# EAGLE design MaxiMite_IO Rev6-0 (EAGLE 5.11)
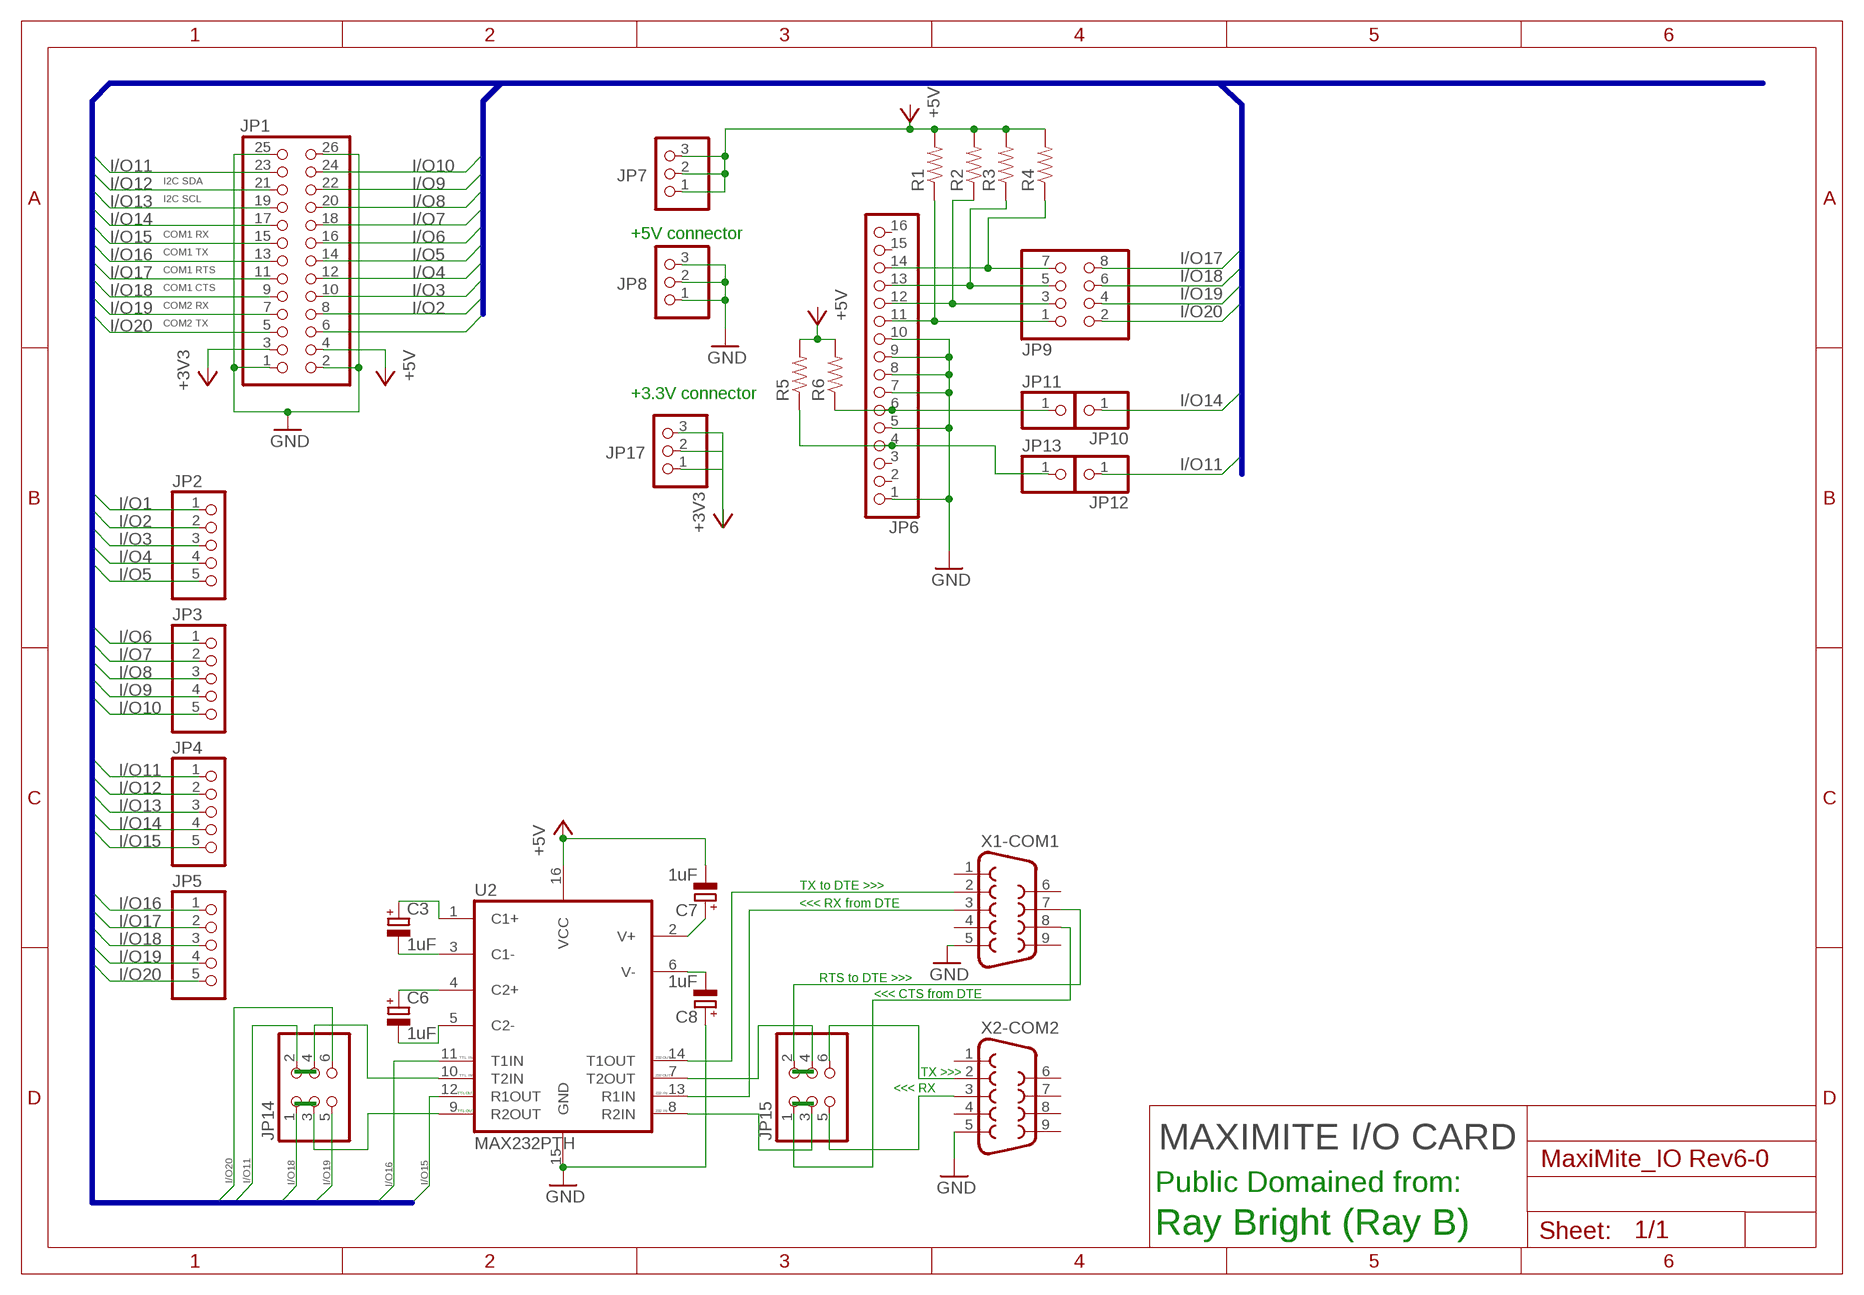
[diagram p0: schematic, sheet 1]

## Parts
C3  1uF  CPOL-EUE2,5-6E  [E2,5-6E]
C6  1uF  CPOL-EUE2,5-6E  [E2,5-6E]
C7  1uF  CPOL-EUE2,5-6E  [E2,5-6E]
C8  1uF  CPOL-EUE2,5-6E  [E2,5-6E]
JP1  PINHD-2X13  [2X13]
JP2  PINHD-1X5  [1X05]
JP3  PINHD-1X5  [1X05]
JP4  PINHD-1X5  [1X05]
JP5  PINHD-1X5  [1X05]
JP6  PINHD-1X16  [1X16]
JP7  PINHD-1X3  [1X03]
JP8  PINHD-1X3  [1X03]
JP9  PINHD-2X4  [2X04]
JP10  PINHD-1X1  [1X01]
JP11  PINHD-1X1  [1X01]
JP12  PINHD-1X1  [1X01]
JP13  PINHD-1X1  [1X01]
JP14  PINHD-2X3  [2X03]
JP15  PINHD-2X3  [2X03]
JP17  PINHD-1X3  [1X03]
R1  RESISTORPTH-1/4W  [AXIAL-0.4]
R2  RESISTORPTH-1/4W  [AXIAL-0.4]
R3  RESISTORPTH-1/4W  [AXIAL-0.4]
R4  RESISTORPTH-1/4W  [AXIAL-0.4]
R5  RESISTORPTH-1/4W  [AXIAL-0.4]
R6  RESISTORPTH-1/4W  [AXIAL-0.4]
U2  MAX232PTH  [DIL16]
X1-COM1  DB9FEMALE  [DB9]
X2-COM2  DB9FEMALE  [DB9]

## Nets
+3V3: JP1.3 JP17.1 JP17.2 JP17.3
+5V: C7.- JP1.4 JP7.1 JP7.2 JP7.3 R1.P$2 R2.P$2 R3.P$2 R4.P$2 R5.P$2 R6.P$2 U2.16(VCC)
GND: C8.+ JP1.1 JP1.2 JP1.25 JP1.26 JP6.1 JP6.5 JP6.7 JP6.8 JP6.9 JP6.10 JP8.1 JP8.2 JP8.3 U2.15(GND) X1-COM1.5 X2-COM2.5
I/O1: JP1.6 JP2.1
I/O2: JP1.8 JP2.2
I/O3: JP1.10 JP2.3
I/O4: JP1.12 JP2.4
I/O5: JP1.14 JP2.5
I/O6: JP1.16 JP3.1
I/O7: JP1.18 JP3.2
I/O8: JP1.20 JP3.3
I/O9: JP1.22 JP3.4
I/O10: JP1.24 JP3.5
I/O11: JP1.23 JP4.1 JP12.1 JP14.2
I/O12: JP1.21 JP4.2
I/O13: JP1.19 JP4.3
I/O14: JP1.17 JP4.4 JP10.1
I/O15: JP1.15 JP4.5 U2.12(R1OUT)
I/O16: JP1.13 JP5.1 U2.11(T1IN)
I/O17: JP1.11 JP5.2 JP9.8
I/O18: JP1.9 JP5.3 JP9.6 JP14.1
I/O19: JP1.7 JP5.4 JP9.4 JP14.5
I/O20: JP1.5 JP5.5 JP9.2 JP14.6
LCD_D4: JP6.11 JP9.1 R1.P$1
LCD_D5: JP6.12 JP9.3 R2.P$1
LCD_D6: JP6.13 JP9.5 R3.P$1
LCD_D7: JP6.14 JP9.7 R4.P$1
LCD_EN: JP6.6 JP11.1 R6.P$1
LCD_RS: JP6.4 JP13.1 R5.P$1
N$18: C3.+ U2.1(C1+)
N$19: C3.- U2.3(C1-)
N$20: C6.+ U2.4(C2+)
N$21: C6.- U2.5(C2-)
N$22: C8.- U2.6(V-)
N$23: C7.+ U2.2(V+)
N$24: JP14.4 U2.10(T2IN)
N$25: JP14.3 U2.9(R2OUT)
N$26: JP15.4 U2.7(T2OUT)
N$27: JP15.3 U2.8(R2IN)
N$28: JP15.6 X2-COM2.2
N$29: JP15.5 X2-COM2.3
N$30: JP15.2 X1-COM1.7
N$31: JP15.1 X1-COM1.8
N$32: U2.14(T1OUT) X1-COM1.2
N$33: U2.13(R1IN) X1-COM1.3
Unconnected: JP6.2 JP6.3 JP6.15 JP6.16 X1-COM1.1 X1-COM1.4 X1-COM1.6 X1-COM1.9 X2-COM2.1 X2-COM2.4 X2-COM2.6 X2-COM2.7 X2-COM2.8 X2-COM2.9

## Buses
I/O[1..20]

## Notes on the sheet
- I2C SDA
- I2C SCL
- COM1 RX | +5V connector
- COM1 TX
- COM1 RTS
- COM1 CTS
- COM2 RX
- COM2 TX
- +3.3V connector
- TX to DTE >>>
- <<< RX from DTE
- RTS to DTE >>>
- <<< CTS from DTE
- TTL IN | 232 OUT
- TTL IN | 232 OUT | TX >>>
- <<< RX
- TTL OUT | 232 IN
- TTL OUT | 232 IN
- MAXIMITE I/O CARD
- Public Domained from: | Freeware from:
- Ray Bright (Ray B)

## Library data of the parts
C3 C6-C8 = rcl:CPOL-EU: POLARIZED CAPACITOR, European symbol
JP1 = 0~MaxiMite:PINHD-2X13: PIN HEADER
JP2-JP5 = pinhead:PINHD-1X5: PIN HEADER
JP6 = pinhead:PINHD-1X16: PIN HEADER
JP7 JP8 JP17 = 0~MaxiMite:PINHD-1X3: PIN HEADER
JP9 = pinhead:PINHD-2X4: PIN HEADER
JP10-JP13 = pinhead:PINHD-1X1: PIN HEADER
JP14 JP15 = 0~MaxiMite:PINHD-2X3: PIN HEADER
R1-R6 = MaxiMite:RESISTOR: Resistor
U2 = 0~MaxiMite:MAX232: RS232 Transceiver Very common IC. This is generically called 'MAX232', but works with the 3V equivalent MAX3232 generic ICs. Field tested and mother approved. Spark Fun Electronics SKU : COM-00316 (DIP) and COM-00589 (SMD)
X1-COM1 X2-COM2 = 0~MaxiMite:DB9: DB9 Connector Standard DB9 (D-Sub 9) serial connector. Can be used for CAN bus as well as RS485 and RS232. Footprint production proven. Spark Fun Electronics SKU : PRT-00429

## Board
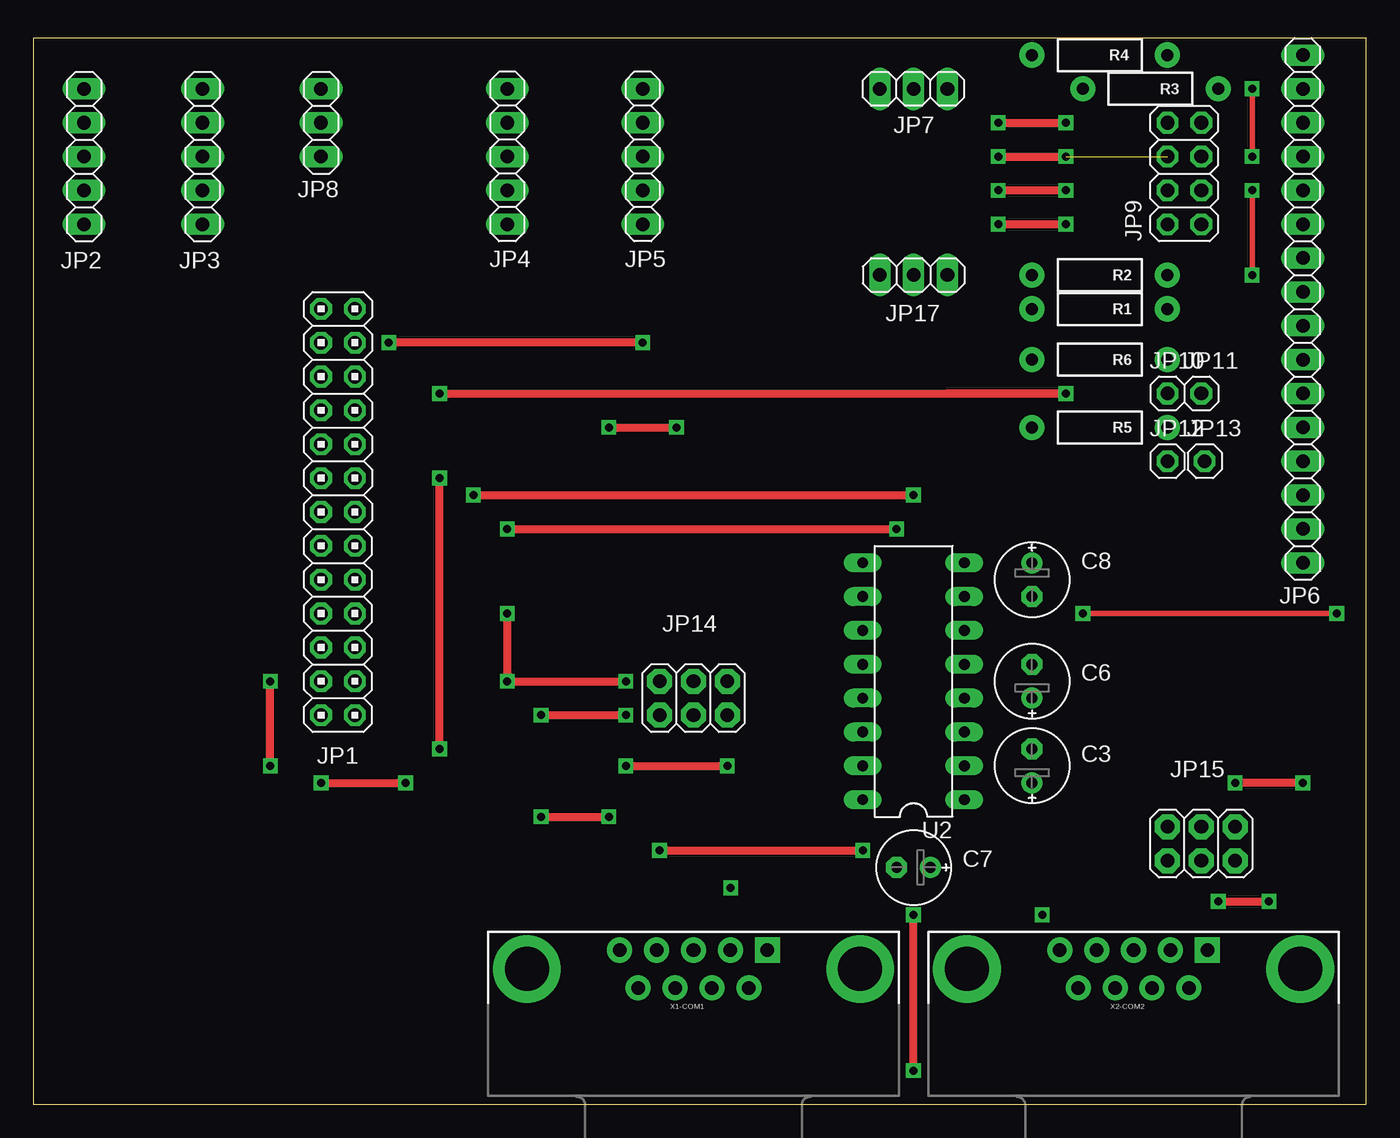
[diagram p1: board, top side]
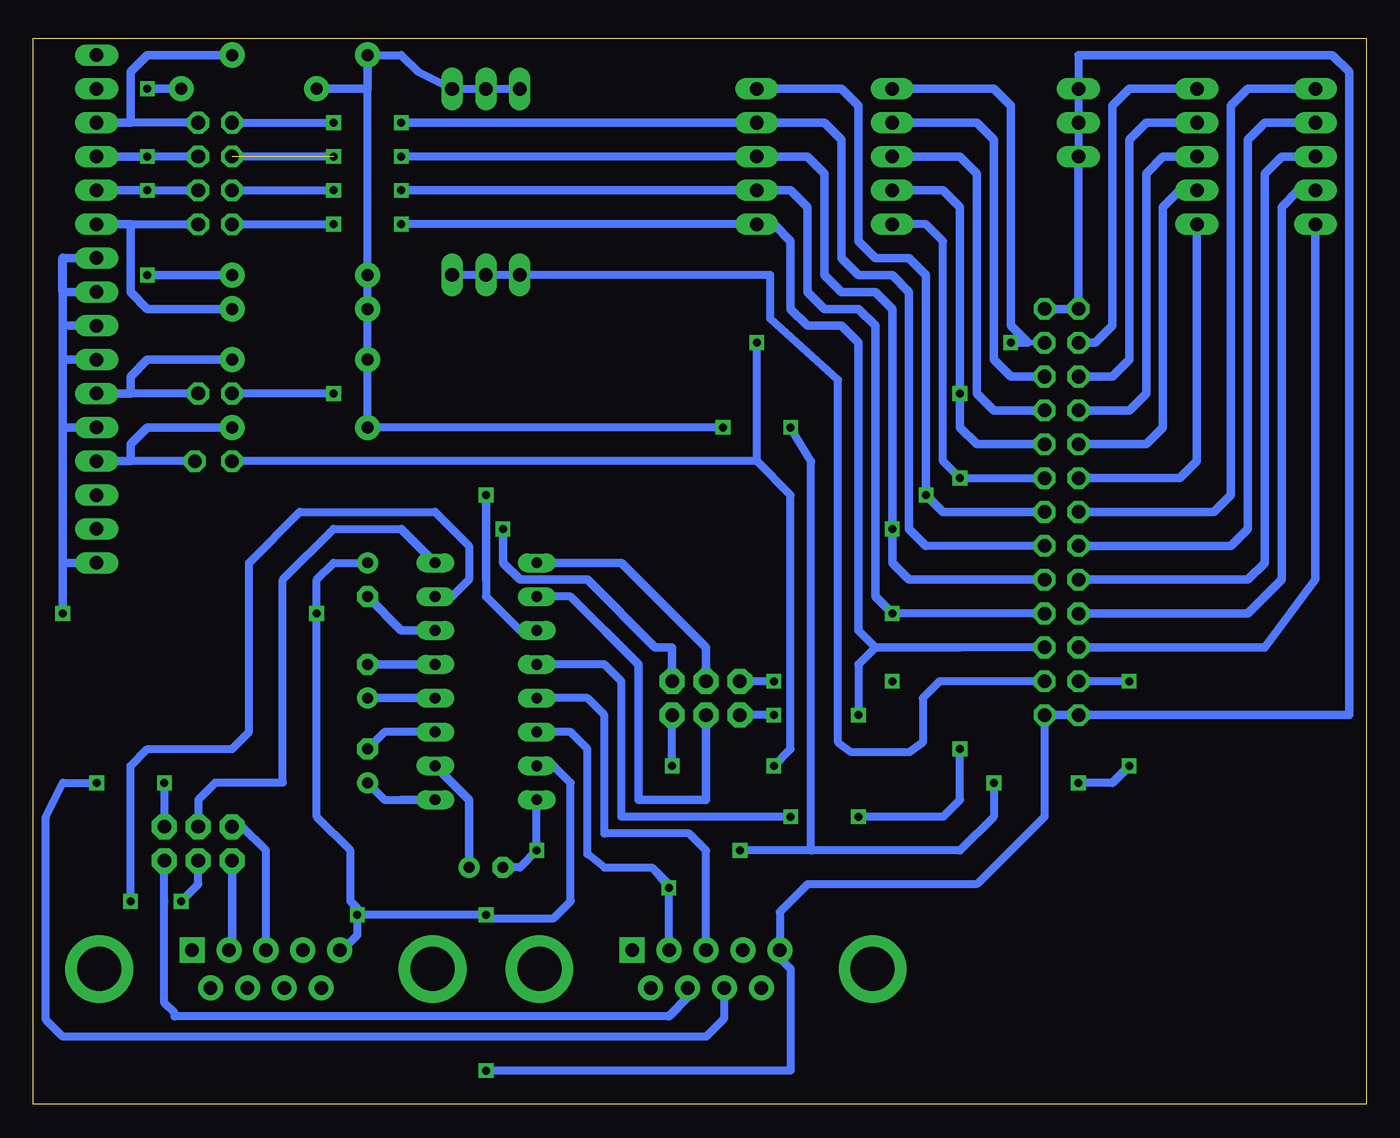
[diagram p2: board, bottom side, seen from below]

Size 100 x 80 mm. Coordinates in mm from the lower left corner, seen from the top.
Outline: 0,0 100,0 100,80 0,80 0,0
Copper layers (1*16): Top 0.035mm / dielectric 1.5mm / Bottom 0.035mm
Design rules "SparkFun_1": minimum track width 25mil, minimum drill 20mil, track to track 25mil, track to pad 8mil, pad to pad 8mil, via to via 8mil, smd to smd 8mil, copper to edge 10mil, drill to drill 8mil, minimum pad ring 12mil, minimum via ring 10mil, stop-mask expansion 4mil, vias tented up to drill 25mil, thermal gap 10mil

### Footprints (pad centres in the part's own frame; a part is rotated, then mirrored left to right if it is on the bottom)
E2,5-6E = drill 0.813 pad 1.575 round: + -1.27,0 | drill 0.813 pad 1.575 octagon: - 1.27,0
2X13 = drill 1.016 octagon: 1 -15.24,-1.27; 2 -15.24,1.27; 3 -12.7,-1.27; 4 -12.7,1.27; 5 -10.16,-1.27; 6 -10.16,1.27; 7 -7.62,-1.27; 8 -7.62,1.27; 9 -5.08,-1.27; 10 -5.08,1.27; 11 -2.54,-1.27; 12 -2.54,1.27; 13 0,-1.27; 14 0,1.27; 15 2.54,-1.27; 16 2.54,1.27; 17 5.08,-1.27; 18 5.08,1.27; 19 7.62,-1.27; 20 7.62,1.27; 21 10.16,-1.27; 22 10.16,1.27; 23 12.7,-1.27; 24 12.7,1.27; 25 15.24,-1.27; 26 15.24,1.27
1X05 = drill 1.016 long: 1 -5.08,0; 2 -2.54,0; 3 0,0; 4 2.54,0; 5 5.08,0
1X16 = drill 1.016 long: 1 -19.05,0; 2 -16.51,0; 3 -13.97,0; 4 -11.43,0; 5 -8.89,0; 6 -6.35,0; 7 -3.81,0; 8 -1.27,0; 9 1.27,0; 10 3.81,0; 11 6.35,0; 12 8.89,0; 13 11.43,0; 14 13.97,0; 15 16.51,0; 16 19.05,0
1X03 = drill 1.016 long: 1 -2.54,0; 2 0,0; 3 2.54,0
2X04 = drill 1.016 octagon: 1 -3.81,-1.27; 2 -3.81,1.27; 3 -1.27,-1.27; 4 -1.27,1.27; 5 1.27,-1.27; 6 1.27,1.27; 7 3.81,-1.27; 8 3.81,1.27
1X01 = drill 1.016 octagon: 1 0,0
2X03 = drill 1.016 pad 1.88 octagon: 1 -2.54,-1.27; 2 -2.54,1.27; 3 0,-1.27; 4 0,1.27; 5 2.54,-1.27; 6 2.54,1.27
AXIAL-0.4 = drill 0.9 pad 1.88 round: P$1 -5.08,0; P$2 5.08,0
DIL16 = drill 0.813 long: 1 -8.89,-3.81; 2 -6.35,-3.81; 3 -3.81,-3.81; 4 -1.27,-3.81; 5 1.27,-3.81; 6 3.81,-3.81; 7 6.35,-3.81; 8 8.89,-3.81; 9 8.89,3.81; 10 6.35,3.81; 11 3.81,3.81; 12 1.27,3.81; 13 -1.27,3.81; 14 -3.81,3.81; 15 -6.35,3.81; 16 -8.89,3.81
DB9 = drill 1.016 pad 1.88 square: 1 -5.54,-1.42 | drill 1.016 pad 1.88 round: 2 -2.77,-1.42; 3 0,-1.42; 4 2.77,-1.42; 5 5.54,-1.42; 6 -4.15,1.42; 7 -1.38,1.42; 8 1.38,1.42; 9 4.15,1.42 | drill 3.302 pad 5.08 round: G1 -12.5,0; G2 12.5,0

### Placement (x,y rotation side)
C3  74.93,25.4 90 top
C6  74.93,31.75 90 top
C7  66.04,17.78 180 top
C8  74.93,39.37 270 top
JP1  22.86,44.45 90 top
JP2  3.81,71.12 90 top
JP3  12.7,71.12 90 top
JP4  35.56,71.12 270 top
JP5  45.72,71.12 270 top
JP6  95.25,59.69 90 top
JP7  66.04,76.2 180 top
JP8  21.59,73.66 90 top
JP9  86.36,69.85 90 top
JP10  85.09,53.34 0 top
JP11  87.63,53.34 0 top
JP12  85.09,48.26 0 top
JP13  87.88,48.26 0 top
JP14  49.53,30.48 180 top
JP15  87.63,19.56 180 top
JP17  66.04,62.23 0 top
R1  80.01,59.69 180 top
R2  80.01,62.23 180 top
R3  83.82,76.2 180 top
R4  80.01,78.74 180 top
R5  80.01,50.8 180 top
R6  80.01,55.88 180 top
U2  66.04,31.75 90 top
X1-COM1  49.53,10.16 180 top
X2-COM2  82.55,10.16 180 top

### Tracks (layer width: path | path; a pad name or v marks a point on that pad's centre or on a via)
+3V3
  Bottom 0.61: JP1.3 32,31.75 33.27,30.48 33.27,27.18 34.29,26.42 38.61,26.42 39.62,27.18 39.62,54.36 44.7,58.93 44.7,62.23 JP17.1 JP17.2 JP17.3
+5V  (via drill 0.6)
  Top 0.61: v46.99,19.05 v62.23,19.05 | v21.59,24.13 v27.94,24.13 | v17.78,25.4 v17.78,31.75 | v43.18,50.8 v48.26,50.8
  Bottom 0.61: C7.- 63.5,17.78 v62.23,19.05 U2.16 | v17.78,31.75 JP1.4 | 74.93,76.2 R2.P$2 R1.P$2 R6.P$2 R5.P$2 v48.26,50.8 | 74.93,78.11 74.3,78.74 | JP7.3 JP7.2 JP7.1 71.12,77.47 72.39,78.74 R4.P$2 | v27.94,24.13 27.94,21.59 30.48,19.05 41.66,19.05 | 41.66,19.05 v46.99,19.05 | 19.05,24.13 v21.59,24.13 | 41.66,19.05 41.66,48.26 v43.18,50.8
  Bottom 0.635: R3.P$2 74.93,76.2 74.93,78.11 R4.P$2 | 19.05,24.13 v17.78,25.4
GND  (via drill 0.6)
  Top 0.406: v78.74,36.83 v97.79,36.83
  Top 0.61: v66.04,2.54 v66.04,14.22
  Bottom 0.61: 21.59,78.74 JP8.3 JP8.2 JP8.1 | 75.69,14.22 v66.04,14.22 65.79,13.97 60.96,13.97 59.69,15.24 59.69,24.13 60.96,25.4 U2.15 | X2-COM2.5 76.81,11.58 75.69,12.7 75.69,14.22 | C8.+ 77.47,40.64 78.74,39.37 v78.74,36.83 78.74,21.59 76.2,19.05 76.2,15.24 75.69,14.73 75.69,14.22 | JP1.1 24.13,21.59 29.21,16.51 41.91,16.51 43.99,14.43 X1-COM1.5 43.99,10.97 43.18,10.16 43.18,2.54 v66.04,2.54
  Bottom 0.635: JP1.25 JP1.26 JP8.1 | JP1.1 JP1.2 1.27,29.21 1.27,77.47 2.54,78.74 21.59,78.74 | 97.79,40.64 JP6.1 | 97.79,50.8 JP6.5 | 97.79,55.88 JP6.7 | 97.79,58.42 JP6.8 | JP6.9 97.79,60.96 97.79,58.42 | 97.79,63.5 JP6.10 | 97.79,55.88 97.79,58.42 | 97.79,50.8 97.79,55.88 | 97.79,40.64 97.79,50.8 | v97.79,36.83 97.79,40.64
  Bottom 0.66: 97.79,60.96 97.79,63.5
I/O1
  Bottom 0.635: JP2.1 3.81,39.37 7.62,34.29 JP1.6
I/O2
  Bottom 0.635: JP2.2 5.08,68.58 6.35,67.31 6.35,39.37 8.89,36.83 JP1.8
I/O3
  Bottom 0.635: JP2.3 6.35,71.12 7.62,69.85 7.62,40.64 8.89,39.37 JP1.10
I/O4
  Bottom 0.635: JP1.12 10.16,41.91 8.89,43.18 8.89,72.39 7.62,73.66 JP2.4
I/O5
  Bottom 0.635: JP1.14 11.43,44.45 10.16,45.72 10.16,74.93 8.89,76.2 JP2.5
I/O6
  Bottom 0.635: JP3.1 12.7,48.26 13.97,46.99 JP1.16
I/O7
  Bottom 0.635: JP1.18 16.51,49.53 15.24,50.8 15.24,67.31 13.97,68.58 JP3.2
I/O8
  Bottom 0.635: JP1.20 17.78,52.07 16.51,53.34 16.51,69.85 15.24,71.12 JP3.3
I/O9
  Bottom 0.635: JP1.22 19.05,54.61 17.78,55.88 17.78,72.39 16.51,73.66 JP3.4
I/O10
  Bottom 0.635: JP1.24 20.32,57.15 19.05,58.42 19.05,74.93 17.78,76.2 JP3.5
I/O11  (via drill 0.6)
  Top 0.61: v44.45,25.4 v52.07,25.4 | v45.72,57.15 v26.67,57.15
  Bottom 0.406: 25.4,57.15 JP1.23
  Bottom 0.61: 45.72,48.26 43.18,45.72 43.18,26.67 v44.45,25.4 | v52.07,25.4 JP14.2 | v26.67,57.15 25.4,57.15 | 45.72,48.26 v45.72,57.15 | 45.72,48.26 JP12.1
  Bottom 0.635: 25.4,57.15 26.67,58.42 26.67,74.93 27.94,76.2 JP4.1
I/O12
  Bottom 0.635: JP4.2 29.21,73.66 27.94,72.39 27.94,55.88 26.67,54.61 JP1.21
I/O13
  Bottom 0.635: JP4.3 30.48,71.12 29.21,69.85 29.21,53.34 27.94,52.07 JP1.19
I/O14  (via drill 0.6)
  Top 0.61: 68.58,53.34 v77.47,53.34 v30.48,53.34
  Bottom 0.61: v77.47,53.34 JP10.1
  Bottom 0.635: JP4.4 31.75,68.58 30.48,67.31 v30.48,53.34 30.48,50.8 29.21,49.53 JP1.17
I/O15  (via drill 0.6)
  Top 0.61: v38.1,21.59 v43.18,21.59 | v30.48,26.67 v30.48,46.99
  Bottom 0.61: v43.18,21.59 55.88,21.59 55.88,31.75 57.15,33.02 U2.12 | v38.1,21.59 31.75,21.59 30.48,22.86 v30.48,26.67 | JP1.15 v30.48,46.99 31.75,48.26 31.75,64.77 33.02,66.04 JP4.5
I/O16  (via drill 0.6)
  Top 0.61: v33.02,45.72 v66.04,45.72
  Bottom 0.61: 66.04,39.37 66.04,38.1 63.5,35.56 U2.11
  Bottom 0.635: JP1.13 31.75,44.45 v33.02,45.72 33.02,62.23 34.29,63.5 36.83,63.5 38.1,64.77 38.1,74.93 39.37,76.2 JP5.1 | v66.04,45.72 66.04,39.37
I/O17  (via drill 0.6)
  Top 0.61: v72.39,73.66 v77.47,73.66
  Bottom 0.61: JP1.11 33.02,41.91 | JP9.8 v77.47,73.66
  Bottom 0.635: 33.02,41.91 34.29,43.18 34.29,60.96 35.56,62.23 38.1,62.23 39.37,63.5 39.37,72.39 40.64,73.66 JP5.2 v72.39,73.66
I/O18  (via drill 0.6)  (1 unrouted)
  Top 0.61: v35.56,43.18 v64.77,43.18 | v72.39,71.12 v77.47,71.12
  Bottom 0.61: JP5.3 v72.39,71.12 | v77.47,71.12 JP9.6
  Bottom 0.635: JP5.3 41.91,71.12 40.64,69.85 40.64,62.23 39.37,60.96 36.83,60.96 35.56,59.69 v35.56,43.18 35.56,40.64 34.29,39.37 JP1.9 | JP14.1 52.07,34.29 53.34,34.29 58.42,39.37 63.5,39.37 64.77,40.64 v64.77,43.18
I/O19  (via drill 0.6)
  Top 0.61: v44.45,31.75 35.56,31.75 v35.56,36.83 | v72.39,68.58 v77.47,68.58
  Bottom 0.61: v44.45,31.75 JP14.5 | JP1.7 v35.56,36.83 | JP9.4 v77.47,68.58
  Bottom 0.635: v35.56,36.83 36.83,38.1 36.83,58.42 38.1,59.69 40.64,59.69 41.91,60.96 41.91,67.31 43.18,68.58 JP5.4 v72.39,68.58
I/O20  (via drill 0.6)
  Top 0.61: v38.1,29.21 v44.45,29.21 | v72.39,66.04 v77.47,66.04
  Bottom 0.61: 38.1,35.56 36.83,34.29 38.1,33.02 v38.1,29.21 | v44.45,29.21 JP14.6 | JP1.5 30.48,34.29 | JP5.5 v72.39,66.04 | JP9.2 v77.47,66.04
  Bottom 0.635: 38.1,35.56 38.1,57.15 39.37,58.42 41.91,58.42 43.18,59.69 43.18,64.77 44.45,66.04 JP5.5 | 30.48,34.29 36.83,34.29
LCD_D4
  Bottom 0.61: 92.96,66.04 JP9.1
  Bottom 0.635: JP6.11 92.96,66.04 92.71,66.04 92.71,60.96 91.44,59.69 R1.P$1
LCD_D5  (via drill 0.6)
  Top 0.406: v91.44,62.23 v91.44,68.58
  Bottom 0.61: 93.47,68.58 JP9.3
  Bottom 0.635: v91.44,68.58 93.47,68.58 JP6.12 | R2.P$1 v91.44,62.23
LCD_D6  (via drill 0.6)
  Top 0.406: v91.44,71.12 v91.44,76.2
  Bottom 0.61: JP9.5 JP6.13
  Bottom 0.635: v91.44,76.2 R3.P$1 | JP6.13 v91.44,71.12
LCD_D7
  Bottom 0.61: JP9.7 92.71,73.66
  Bottom 0.635: R4.P$1 91.44,78.74 92.71,77.47 92.71,73.66 JP6.14
LCD_EN
  Bottom 0.61: JP11.1 93.22,53.34
  Bottom 0.635: JP6.6 93.22,53.34 92.71,53.34 92.71,54.61 91.44,55.88 R6.P$1
LCD_RS
  Bottom 0.61: JP13.1 93.73,48.26
  Bottom 0.635: JP6.4 93.73,48.26 93.22,48.26 92.71,48.26 92.71,49.53 91.44,50.8 R5.P$1
N$1  (via drill 0.6)
  other vias: 44.45,29.21
N$2  (via drill 0.6)
  other vias: 91.44,71.12
N$3  (via drill 0.6)
  other vias: 38.1,29.21
N$4  (via drill 0.6)
  other vias: 44.45,25.4
N$5  (via drill 0.6)
  other vias: 77.47,66.04
N$12  (via drill 0.6)
  other vias: 72.39,66.04
N$15  (via drill 0.6)
  other vias: 17.78,31.75
N$18
  Bottom 0.61: C3.+ 73.66,22.86 72.39,22.86
  Bottom 0.635: U2.1 72.39,22.86
N$19
  Bottom 0.61: U2.3 73.66,27.94 C3.-
N$20
  Bottom 0.635: U2.4 C6.+
N$21
  Bottom 0.635: U2.5 C6.-
N$22
  Bottom 0.635: U2.6 72.39,35.56 C8.-
N$23
  Bottom 0.635: U2.2 67.31,22.86 C7.+
N$24
  Bottom 0.61: U2.10 59.69,38.1 57.15,35.56
  Bottom 0.635: 57.15,35.56 54.61,33.02 54.61,22.86 49.53,22.86 JP14.4
N$25
  Bottom 0.635: U2.9 55.88,40.64 49.53,34.29 JP14.3
N$26  (via drill 0.6)
  Top 0.61: v88.9,15.24 v92.71,15.24
  Bottom 0.61: U2.7 68.58,38.1 67.31,39.37 67.31,41.91 69.85,44.45 80.01,44.45 83.82,40.64 83.82,27.94 85.09,26.67 91.44,26.67 92.71,25.4 v92.71,15.24 | v88.9,15.24 87.63,16.51 JP15.4
N$27
  Bottom 0.61: 72.39,43.18 77.47,43.18 81.28,39.37 81.28,24.13 86.36,24.13 87.63,22.86 JP15.3
  Bottom 0.635: 72.39,43.18 U2.8
N$28
  Bottom 0.635: JP15.6 85.09,11.43 X2-COM2.2
N$29
  Bottom 0.61: X2-COM2.3 82.55,19.05 84.33,20.83 JP15.5
N$30
  Bottom 0.61: JP15.2 90.17,17.78 90.17,15.24 90.17,7.62 89.41,6.86 89.41,6.6 52.32,6.6 | 50.91,8.02 X1-COM1.7
  Bottom 0.635: 52.32,6.6 50.91,8.02
N$31  (via drill 0.6)
  Top 0.61: v95.25,24.13 v90.17,24.13
  Bottom 0.61: X1-COM1.8 48.15,6.46 49.53,5.08 97.79,5.08 99.06,6.35 99.06,21.59 97.79,24.13 v95.25,24.13 | v90.17,24.13 JP15.1
N$32  (via drill 0.6)
  Bottom 0.61: U2.14 59.69,27.94 58.42,26.67 58.42,18.8 57.15,17.78 53.59,17.78 | X1-COM1.2 52.32,11.6 v52.32,16.26 | v52.32,16.26 53.59,17.78 | 53.59,17.78 52.32,16.51 v52.32,16.26
N$33
  Bottom 0.61: X1-COM1.3 49.53,19.05 50.8,20.32 57.15,20.32 57.15,29.21 58.42,30.48 U2.13
N$36  (via drill 0.6)
  other vias: 30.48,26.67
N$38  (via drill 0.6)
  other vias: 44.45,31.75
N$39  (via drill 0.6)
  other vias: 35.56,31.75
N$46  (via drill 0.6)
  other vias: 66.04,2.54
N$47  (via drill 0.6)
  other vias: 66.04,14.22
N$48  (via drill 0.6)
  other vias: 75.69,14.22

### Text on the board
_tsilk: +5V | I/O5 | I/O10 | 0V | I/O11 | I/O16 | 0V | 0V | I/O1 | I/O6 | I/O15 | I/O20 | +3V3 | 0V | 0V | I/O10 | I/O1 | I/O20 | 5 | 3 | 1 | +5V | +3.3V | 0V | 6 | 6 | 4 | 2 | 3 | 5 | 1 | 6 | 2 | 4 | COM1 | COM2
